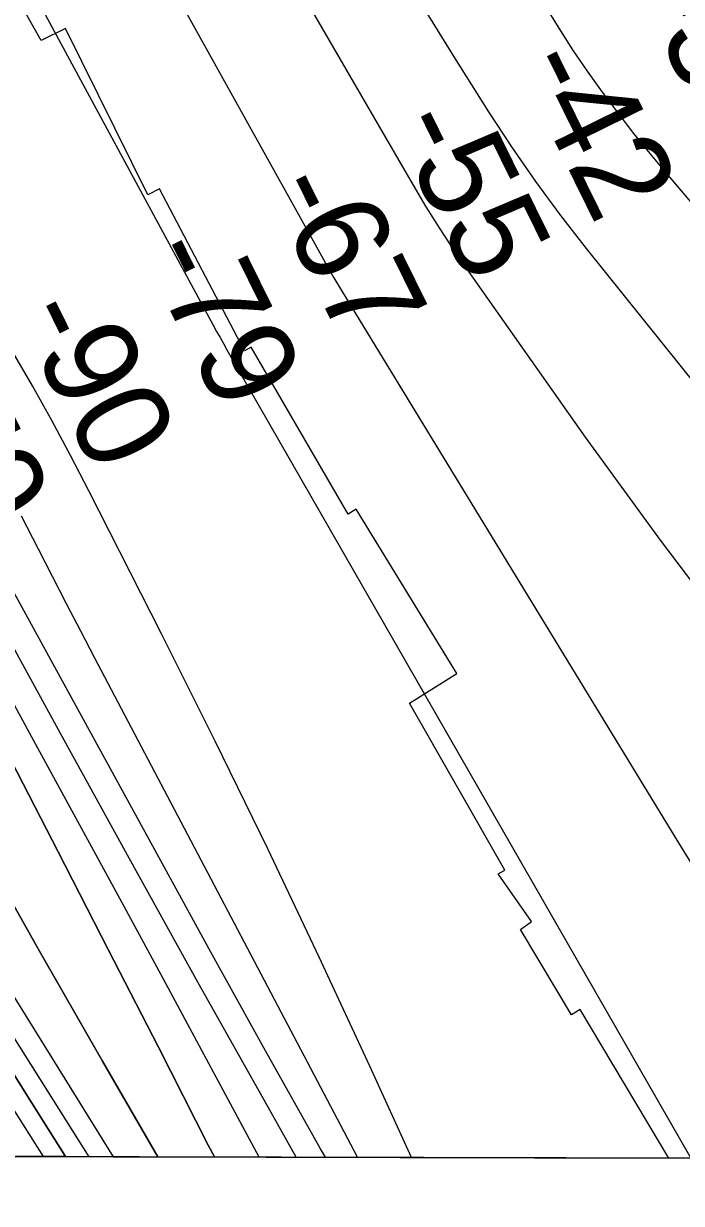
# Model space of a CAD drawing. Extents: x 3177185 to 3215018, y 812988 to 838321.
# Drawn here: x 3198368 to 3198839, y 818326 to 819169 of the extents above; entities that cross this region are included whole.
import ezdxf

# ---------------------------------------------------------------- set-up
doc = ezdxf.new("R2010")
doc.units = 0
for name, color, linetype in [('V-GRID-FRAM', 7, 'Continuous'), ('V-RIVR-RANG', 7, 'Continuous'), ('V-RRAP-RVMT', 7, 'Continuous'), ('V-TOPO-DPTH', 7, 'Continuous'), ('V-TOPO-MAJR', 7, 'Continuous'), ('V-TOPO-MINR', 7, 'Continuous')]:
    doc.layers.add(name, color=color, linetype=linetype)

msp = doc.modelspace()

# ---------------------------------------------------------------- linework, layer by layer
at = {"layer": 'V-GRID-FRAM'}
msp.add_lwpolyline([(3181402.42, 836586.07), (3212801.61, 836513), (3212767.22, 818326.14), (3181352.16, 818399.25), (3181402.42, 836586.07)], dxfattribs=at)
at = {"layer": 'V-RRAP-RVMT'}
for p, q in [((3198381.06, 819157.21), (3198326.77, 819254.14)), ((3198398.35, 819165.78), (3198381.06, 819157.21)), ((3198457.28, 819046.97), (3198398.35, 819165.78)), ((3198465.64, 819051.25), (3198457.28, 819046.97)), ((3198526.45, 818935.45), (3198465.64, 819051.25)), ((3198531, 818938.15), (3198526.45, 818935.45)), ((3198600.37, 818818.84), (3198531, 818938.15)), ((3198606.06, 818822.33), (3198600.37, 818818.84)), ((3198678.11, 818704.87), (3198606.06, 818822.33)), ((3198644.27, 818683.67), (3198678.11, 818704.87)), ((3198712.31, 818564.38), (3198644.27, 818683.67)), ((3198707.75, 818561.81), (3198712.31, 818564.38)), ((3198731.54, 818527.53), (3198707.75, 818561.81)), ((3198723.54, 818521.91), (3198731.54, 818527.53)), ((3198760.07, 818460.92), (3198723.54, 818521.91)), ((3198766.3, 818464.62), (3198760.07, 818460.92)), ((3198829.67, 818358.58), (3198766.3, 818464.62)), ((3198298, 818359.82), (3198829.67, 818358.58))]:
    msp.add_line(p, q, dxfattribs=at)
at = {"layer": 'V-TOPO-DPTH'}
for points in [[(3197827.26, 819387.33), (3198034.41, 819014.08), (3198048.82, 818988.41), (3198063.42, 818962.85), (3198078.27, 818937.43), (3198093.3, 818912.12), (3198099.44, 818901.88), (3198111.58, 818881.8), (3198123.8, 818861.75), (3198136.12, 818841.78), (3198148.51, 818821.85), (3198164.32, 818796.59), (3198168.84, 818789.31), (3198173.34, 818782.01), (3198177.8, 818774.69), (3198182.23, 818767.35), (3198221.89, 818701.26), (3198246.22, 818660.91), (3198270.68, 818620.65), (3198295.32, 818580.49), (3198320.09, 818540.42), (3198432.49, 818359.5), (3198398.39, 818359.58)], [(3197827.26, 819387.33), (3198034.41, 819014.08), (3198048.82, 818988.41), (3198063.42, 818962.85), (3198078.27, 818937.43), (3198093.3, 818912.12), (3198099.44, 818901.88), (3198111.58, 818881.8), (3198123.8, 818861.75), (3198136.12, 818841.78), (3198148.51, 818821.85), (3198164.32, 818796.59), (3198168.84, 818789.31), (3198173.34, 818782.01), (3198177.8, 818774.69), (3198182.23, 818767.35), (3198221.89, 818701.26), (3198246.22, 818660.91), (3198270.68, 818620.65), (3198295.32, 818580.49), (3198320.09, 818540.42), (3198432.49, 818359.5)], [(3198432.49, 818359.5), (3198464.39, 818359.43), (3198424.8, 818427.72), (3198378.97, 818508.11), (3198244.61, 818746.78), (3198229.21, 818773.7), (3198213.56, 818800.47), (3198197.54, 818827.02), (3198181.28, 818853.43), (3198124.09, 818944.81), (3198079.41, 819017.01), (3198035.2, 819089.5), (3197991.7, 819162.41), (3197948.67, 819235.62)], [(3197948.67, 819235.62), (3197991.7, 819162.41), (3198035.2, 819089.5), (3198079.41, 819017.01), (3198124.09, 818944.81), (3198181.28, 818853.43), (3198197.54, 818827.02), (3198213.56, 818800.47), (3198229.21, 818773.7), (3198244.61, 818746.78), (3198378.97, 818508.11), (3198424.8, 818427.72), (3198464.39, 818359.43)], [(3198398.39, 818359.58), (3198369.94, 818404.72), (3198313.23, 818495.3), (3198256.7, 818585.99), (3198152.22, 818754.17), (3198148.11, 818760.89), (3198144.05, 818767.63), (3198140.08, 818774.42), (3198136.17, 818781.25), (3197962.83, 819088.03), (3197905.07, 819193.56)], [(3197905.07, 819193.56), (3197962.83, 819088.03), (3198136.17, 818781.25), (3198140.08, 818774.42), (3198144.05, 818767.63), (3198148.11, 818760.89), (3198152.22, 818754.17), (3198256.7, 818585.99), (3198313.23, 818495.3), (3198369.94, 818404.72), (3198398.39, 818359.58), (3198362.64, 818359.67)], [(3198464.39, 818359.43), (3198504.8, 818359.34), (3198500.47, 818367.83), (3198464.76, 818437.7), (3198428.95, 818507.52), (3198393.07, 818577.31), (3198346.96, 818666.85)], [(3198346.96, 818666.85), (3198393.07, 818577.31), (3198428.95, 818507.52), (3198464.76, 818437.7), (3198500.47, 818367.83), (3198504.8, 818359.34)], [(3198504.8, 818359.34), (3199540.71, 818356.92)]]:
    msp.add_lwpolyline(points, dxfattribs=at)
at = {"layer": 'V-TOPO-MAJR'}
for points in [[(3198536.92, 818359.26), (3198468.34, 818486.32), (3198437.12, 818544.05), (3198405.82, 818601.75), (3198374.42, 818659.39), (3198342.95, 818716.99), (3198296.61, 818801.61), (3198288.15, 818816.81), (3198279.56, 818831.93), (3198270.76, 818846.94), (3198261.83, 818861.87), (3198205.14, 818955.16), (3198189.1, 818980.86), (3198172.66, 819006.29), (3198155.62, 819031.31), (3198138.17, 819056.08), (3198120.45, 819080.66), (3198102.76, 819105.26), (3198085.13, 819129.91), (3198067.53, 819154.58), (3198018.36, 819223.67)], [(3198741.19, 819181.74), (3198750.89, 819166.04), (3198760.88, 819150.54), (3198771.32, 819135.32), (3198782.04, 819120.3), (3198793.13, 819105.54), (3198804.43, 819090.94), (3198816.02, 819076.58), (3198827.82, 819062.38), (3198970.15, 818894.67)]]:
    msp.add_lwpolyline(points, dxfattribs=at)
at = {"layer": 'V-TOPO-MINR'}
for points in [[(3197754.1, 820868.36), (3197895.12, 820450.93), (3197927.33, 820358.23), (3197960.58, 820265.92), (3197995.41, 820174.18), (3198031.29, 820082.84), (3198091.12, 819934.3), (3198098.07, 819917.6), (3198105.28, 819901.03), (3198112.88, 819884.63), (3198120.74, 819868.34), (3198197.62, 819713.73), (3198244.74, 819620.56), (3198292.71, 819527.83), (3198341.95, 819435.77), (3198392.03, 819344.15), (3198581.28, 819003.47), (3198585.76, 818995.52), (3198590.3, 818987.62), (3198594.94, 818979.77), (3198599.64, 818971.96), (3198834.6, 818586.96), (3198865.51, 818536.74)], [(3197277.79, 820810.78), (3197401.73, 820396.89), (3197436.71, 820284.8), (3197473.4, 820173.3), (3197512.67, 820062.68), (3197553.64, 819952.65), (3197626.76, 819763.05), (3197632.6, 819748.31), (3197638.61, 819733.65), (3197644.89, 819719.1), (3197651.35, 819704.62), (3197787.76, 819406.19), (3197839.85, 819296), (3197893.8, 819186.76), (3197950.54, 819078.95), (3198009.15, 818972.08), (3198113.19, 818788), (3198121.27, 818773.95), (3198129.5, 818759.98), (3198137.92, 818746.14), (3198146.49, 818732.38), (3198382.49, 818359.62)], [(3197737.63, 820706.06), (3197773.23, 820594.78), (3197809.94, 820483.88), (3197848.31, 820373.54), (3197887.78, 820263.57), (3198025.31, 819889.32), (3198027.9, 819882.51), (3198030.58, 819875.73), (3198033.41, 819869.02), (3198036.33, 819862.34), (3198092.69, 819737.17), (3198124.61, 819668.31), (3198157.52, 819599.94), (3198191.91, 819532.3), (3198227.3, 819465.16), (3198504.02, 818953.79), (3198506.42, 818949.4), (3198508.83, 818945.03), (3198511.28, 818940.67), (3198513.76, 818936.32), (3198845.26, 818358.54)], [(3197827.26, 819387.33), (3198034.41, 819014.08), (3198048.82, 818988.41), (3198063.42, 818962.85), (3198078.27, 818937.43), (3198093.3, 818912.12), (3198099.44, 818901.88), (3198111.58, 818881.8), (3198123.8, 818861.75), (3198136.12, 818841.78), (3198148.51, 818821.85), (3198164.32, 818796.59), (3198168.84, 818789.31), (3198173.34, 818782.01), (3198177.8, 818774.69), (3198182.23, 818767.35), (3198221.89, 818701.26), (3198246.22, 818660.91), (3198270.68, 818620.65), (3198295.32, 818580.49), (3198320.09, 818540.42), (3198432.49, 818359.5)], [(3198645.62, 818359.01), (3198615.8, 818424.32), (3198579.71, 818502.08), (3198542.98, 818579.54), (3198505.3, 818656.53), (3198466.98, 818733.21), (3198415.12, 818835.41), (3198402.02, 818860.64), (3198388.61, 818885.7), (3198374.73, 818910.5), (3198360.54, 818935.14), (3198068.53, 819351.22)], [(3197891.8, 819244.61), (3198154.57, 818775.85), (3198155.75, 818773.78), (3198156.36, 818772.76), (3198156.97, 818771.73), (3198179.13, 818735.21), (3198190.88, 818715.96), (3198202.7, 818696.74), (3198214.61, 818677.59), (3198226.59, 818658.48), (3198414.99, 818359.54)], [(3197948.67, 819235.62), (3197991.7, 819162.41), (3198035.2, 819089.5), (3198079.41, 819017.01), (3198124.09, 818944.81), (3198181.28, 818853.43), (3198197.54, 818827.02), (3198213.56, 818800.47), (3198229.21, 818773.7), (3198244.61, 818746.78), (3198378.97, 818508.11), (3198424.8, 818427.72), (3198464.39, 818359.43)], [(3198584.11, 818359.15), (3198580.69, 818365.14), (3198541.3, 818435.29), (3198502.32, 818505.68), (3198349.13, 818785.06), (3198331.4, 818816.9), (3198313.38, 818848.58), (3198294.94, 818880.02), (3198276.22, 818911.29), (3198164.01, 819095.95), (3198127.18, 819155.25), (3198089.58, 819214.05)], [(3198557.46, 819208.12), (3198646.83, 819053.83), (3198655.97, 819038.52), (3198665.39, 819023.37), (3198675.2, 819008.49), (3198685.29, 818993.78), (3198769.84, 818873.89), (3198823.48, 818800.2), (3198878.55, 818727.63)], [(3197905.07, 819193.56), (3197962.83, 819088.03), (3198136.17, 818781.25), (3198140.08, 818774.42), (3198144.05, 818767.63), (3198148.11, 818760.89), (3198152.22, 818754.17), (3198256.7, 818585.99), (3198313.23, 818495.3), (3198369.94, 818404.72), (3198398.39, 818359.58)], [(3198563.37, 818359.2), (3198543.13, 818395.04), (3198493.33, 818483.83), (3198443.95, 818572.84), (3198394.83, 818662), (3198322.86, 818793.33), (3198309.77, 818816.85), (3198296.47, 818840.26), (3198282.85, 818863.48), (3198269.02, 818886.58), (3198183.61, 819027.15), (3198157.65, 819068.85), (3198131.09, 819110.16), (3198103.63, 819150.88), (3198075.59, 819191.21)], [(3198648.62, 819190.1), (3198676.36, 819145.04), (3198700.75, 819106.39), (3198717.22, 819081.24), (3198734.25, 819056.5), (3198752.13, 819032.35), (3198770.56, 819008.61), (3198850.16, 818909.63)], [(3198607.15, 818359.1), (3198419.45, 818715.85), (3198409.28, 818735.26), (3198399.16, 818754.7), (3198389.1, 818774.17), (3198379.09, 818793.67), (3198367.01, 818817.32)], [(3198346.96, 818666.85), (3198393.07, 818577.31), (3198428.95, 818507.52), (3198464.76, 818437.7), (3198500.47, 818367.83), (3198504.8, 818359.34)]]:
    msp.add_lwpolyline(points, dxfattribs=at)

# ---------------------------------------------------------------- texts
at = {"layer": 'V-RIVR-RANG'}
for s, p in [('-33', (3198808.79, 819187.95)), ('-42', (3198720.97, 819139.94)), ('-55', (3198630.81, 819096.66)), ('-67', (3198541.59, 819051.48)), ('-79', (3198452.95, 819005.12)), ('-90', (3198363.03, 818961.37)), ('-70', (3198273.11, 818917.61))]:
    msp.add_text(s, height=67, rotation=296.23692, dxfattribs=at).set_placement(p)

doc.saveas('drawing.dxf')
